(* Logix 5000 project; controller CIP_Sync_Essentials_Sample_Project_2_1 vendor 1 type 14 code 156 rev 34.11; software revision 34.01; part 4 of 4 *)
(* tags used below, declared in another part *)
   ax1_Cip_State_Machine : CIP_Axis_State_Machine;
   Ax1_Current_State : STRING;
   Ax1_Cyclic_Pos_Dis_AOI : CIP_Axis_Disable_Streaming;
   Ax1_Cyclic_Pos_Dis_Err_Description : STRING;
   Ax1_Cyclic_Pos_En_AOI : CIP_Axis_Enable_Streaming;
   Ax1_Cyclic_Pos_En_Err_Description : STRING;
   ax1_cyclic_position_off_request : BOOL;
   ax1_cyclic_position_on_request : BOOL;
   Ax1_Disable_AOI : CIP_Axis_Disable;
   Ax1_Disable_Error_Description : STRING;
   Ax1_Disable_Request_OS : BOOL;
   ax1_disable_streaming_os : BOOL;
   Ax1_Disable_Toggle : BOOL;
   Ax1_Enable_AOI : CIP_Axis_Enable;
   Ax1_Enable_Error_Description : STRING;
   Ax1_Enable_Request_OS : BOOL;
   ax1_enable_streaming_os : BOOL;
   Ax1_Enable_Toggle : BOOL;
   Ax1_Error_Message : STRING;
   Ax1_Extend : BOOL;
   ax1_extend_abs_move : MOTION_INSTRUCTION;
   Ax1_Extend_Target_Pos : DINT;
   Ax1_Fault_Reset_AOI : CIP_Axis_Fault_Reset;
   Ax1_Fault_Reset_Error_Description : STRING;
   Ax1_FAULT_RESET_OS : BOOL;
   Ax1_Fault_Reset_Toggle : BOOL;
   Ax1_Home : BOOL;
   Ax1_Home_AOI : CIP_Axis_Home;
   Ax1_Home_Error_Description : STRING;
   Ax1_Homed : BOOL;
   Ax1_Jog_Fwd : BOOL;
   Ax1_Jog_Rev : BOOL;
   AX1_MAJ1 : MOTION_INSTRUCTION;
   AX1_MAJ2 : MOTION_INSTRUCTION;
   Ax1_MAS1 : MOTION_INSTRUCTION;
   Ax1_Position_Cmd_Rsp_Assy : DINT;
   Ax1_Position_Fbk_Rsp_Assy : DINT;
   Ax1_Quick_Stop_Active : BOOL;
   Ax1_Quick_Stop_AOI : CIP_Axis_Quick_Stop;
   Ax1_Quick_Stop_Error_Description : STRING;
   Ax1_Quick_Stop_MSG : MESSAGE;
   Ax1_Quick_Stop_OS : BOOL;
   Ax1_Quick_Stop_Toggle : BOOL;
   Ax1_Retract : BOOL;
   ax1_retract_abs_move : MOTION_INSTRUCTION;
   ax1_start_home_ons : BOOL;
   Ax1_Stop_Cmd : BOOL;   // Axis Stop Command under normal streaming conditions
   Ax1_Stop_Cmd2 : BOOL;   // Axis Stop Command in the even the axis is disabled (disable or quick stop option code is 1 or 2) or disabled by fault
   Ax1_Stop_Cmd3 : BOOL;   // Axis Stop Command if streaming is disabled
   Ax1_Stop_OS : BOOL;
   Ax1_Stop_OS2 : BOOL;
   Ax1_Stop_OS3 : BOOL;
   Ax1_Streaming_Active : BOOL;
   Ax1_UnwindMsg : MESSAGE;
   Ax1_UpdatePeriodMsg : MESSAGE;
   Ax1_Virtual_Master_Actual_Position : DINT;
   Ax1_Virtual_Master_Cmd_Pos : DINT;
   Axis1_Disabled : BOOL;
   Axis1_Enabled : BOOL;
   Axis1_Faulted : BOOL;
   Axis1_Rotary : AXIS_VIRTUAL;
   AXIS_ONE : CIP_Axis;
   MotionGroup : MOTION_GROUP;

PROGRAM MainProgram   (* main routine MainRoutine_with_CIP_State_Machines *)

ROUTINE Axis1_Routine   (* ladder *)
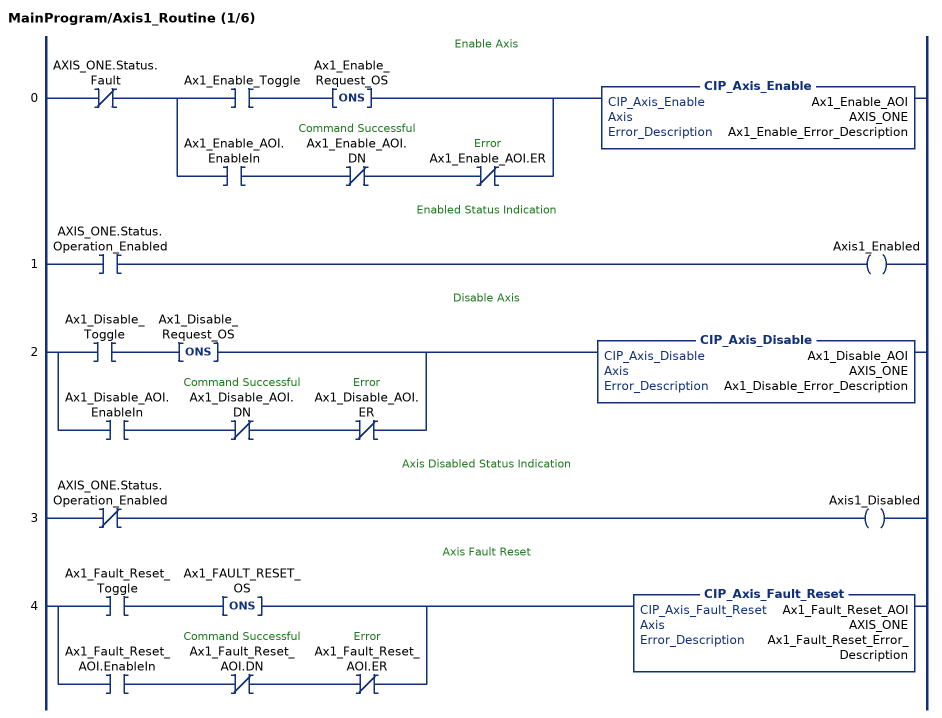
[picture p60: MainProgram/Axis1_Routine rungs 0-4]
   // Enable Axis
   0: XIO(AXIS_ONE.Status.Fault)[XIC(Ax1_Enable_Toggle) ONS(Ax1_Enable_Request_OS) ,XIC(Ax1_Enable_AOI.EnableIn) XIO(Ax1_Enable_AOI.DN) XIO(Ax1_Enable_AOI.ER) ]CIP_Axis_Enable(Ax1_Enable_AOI,AXIS_ONE,Ax1_Enable_Error_Description);
   // Enabled Status Indication
   1: XIC(AXIS_ONE.Status.Operation_Enabled)OTE(Axis1_Enabled);
   // Disable Axis
   2: [XIC(Ax1_Disable_Toggle) ONS(Ax1_Disable_Request_OS) ,XIC(Ax1_Disable_AOI.EnableIn) XIO(Ax1_Disable_AOI.DN) XIO(Ax1_Disable_AOI.ER) ]CIP_Axis_Disable(Ax1_Disable_AOI,AXIS_ONE,Ax1_Disable_Error_Description);
   // Axis Disabled Status Indication
   3: XIO(AXIS_ONE.Status.Operation_Enabled)OTE(Axis1_Disabled);
   // Axis Fault Reset
   4: [XIC(Ax1_Fault_Reset_Toggle) ONS(Ax1_FAULT_RESET_OS) ,XIC(Ax1_Fault_Reset_AOI.EnableIn) XIO(Ax1_Fault_Reset_AOI.DN) XIO(Ax1_Fault_Reset_AOI.ER) ]CIP_Axis_Fault_Reset(Ax1_Fault_Reset_AOI,AXIS_ONE,Ax1_Fault_Reset_Error_Description);
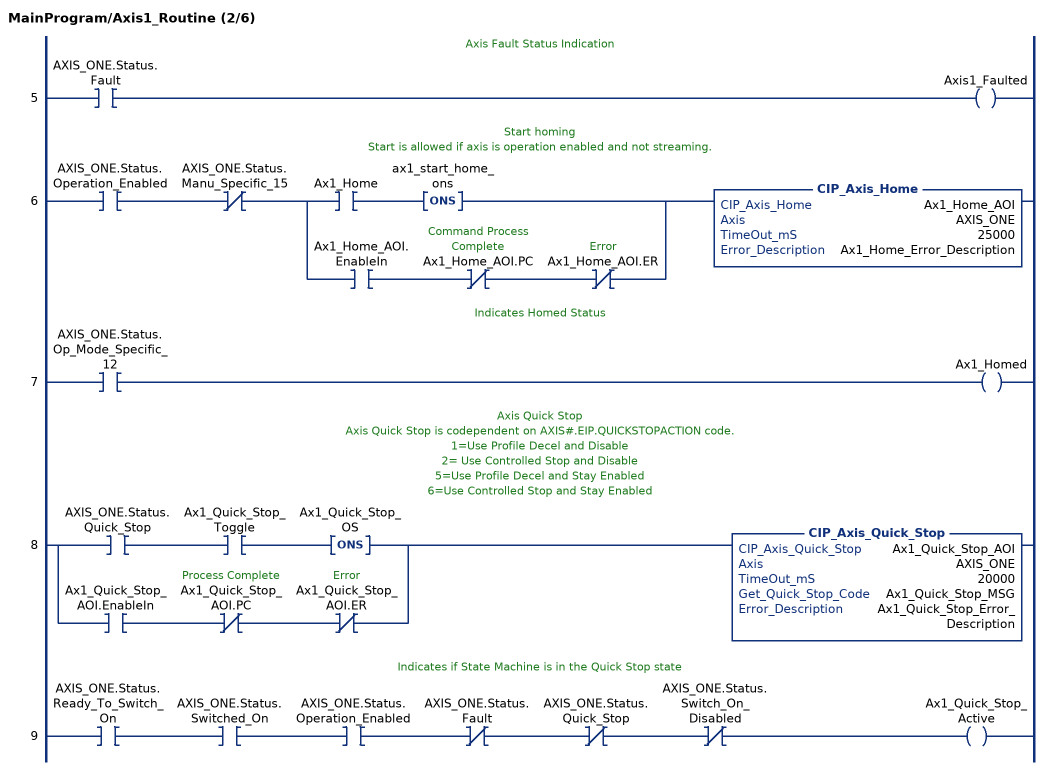
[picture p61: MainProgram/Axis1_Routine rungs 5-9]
   // Axis Fault Status Indication
   5: XIC(AXIS_ONE.Status.Fault)OTE(Axis1_Faulted);
   // Start homing
   // Start is allowed if axis is operation enabled and not streaming.
   6: XIC(AXIS_ONE.Status.Operation_Enabled)XIO(AXIS_ONE.Status.Manu_Specific_15)[XIC(Ax1_Home) ONS(ax1_start_home_ons) ,XIC(Ax1_Home_AOI.EnableIn) XIO(Ax1_Home_AOI.PC) XIO(Ax1_Home_AOI.ER) ]CIP_Axis_Home(Ax1_Home_AOI,AXIS_ONE,25000,Ax1_Home_Error_Description);
   // Indicates Homed Status
   7: XIC(AXIS_ONE.Status.Op_Mode_Specific_12)OTE(Ax1_Homed);
   // Axis Quick Stop
   // Axis Quick Stop is codependent on AXIS#.EIP.QUICKSTOPACTION code.
   // 1=Use Profile Decel and Disable
   // 2= Use Controlled Stop and Disable
   // 5=Use Profile Decel and Stay Enabled
   // 6=Use Controlled Stop and Stay Enabled
   8: [XIC(AXIS_ONE.Status.Quick_Stop) XIC(Ax1_Quick_Stop_Toggle) ONS(Ax1_Quick_Stop_OS) ,XIC(Ax1_Quick_Stop_AOI.EnableIn) XIO(Ax1_Quick_Stop_AOI.PC) XIO(Ax1_Quick_Stop_AOI.ER) ]CIP_Axis_Quick_Stop(Ax1_Quick_Stop_AOI,AXIS_ONE,20000,Ax1_Quick_Stop_MSG,Ax1_Quick_Stop_Error_Description);
   // Indicates if State Machine is in the Quick Stop state
   9: XIC(AXIS_ONE.Status.Ready_To_Switch_On)XIC(AXIS_ONE.Status.Switched_On)XIC(AXIS_ONE.Status.Operation_Enabled)XIO(AXIS_ONE.Status.Fault)XIO(AXIS_ONE.Status.Quick_Stop)XIO(AXIS_ONE.Status.Switch_On_Disabled)OTE(Ax1_Quick_Stop_Active);
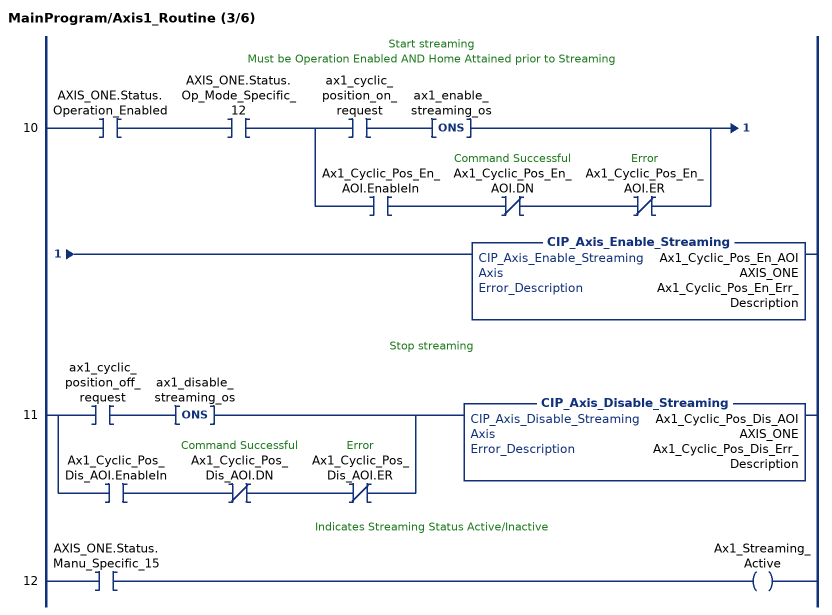
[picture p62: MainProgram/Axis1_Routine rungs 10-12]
   // Start streaming
   // Must be Operation Enabled AND Home Attained prior to Streaming
   10: XIC(AXIS_ONE.Status.Operation_Enabled)XIC(AXIS_ONE.Status.Op_Mode_Specific_12)[XIC(ax1_cyclic_position_on_request) ONS(ax1_enable_streaming_os) ,XIC(Ax1_Cyclic_Pos_En_AOI.EnableIn) XIO(Ax1_Cyclic_Pos_En_AOI.DN) XIO(Ax1_Cyclic_Pos_En_AOI.ER) ]CIP_Axis_Enable_Streaming(Ax1_Cyclic_Pos_En_AOI,AXIS_ONE,Ax1_Cyclic_Pos_En_Err_Description);
   // Stop streaming
   11: [XIC(ax1_cyclic_position_off_request) ONS(ax1_disable_streaming_os) ,XIC(Ax1_Cyclic_Pos_Dis_AOI.EnableIn) XIO(Ax1_Cyclic_Pos_Dis_AOI.DN) XIO(Ax1_Cyclic_Pos_Dis_AOI.ER) ]CIP_Axis_Disable_Streaming(Ax1_Cyclic_Pos_Dis_AOI,AXIS_ONE,Ax1_Cyclic_Pos_Dis_Err_Description);
   // Indicates Streaming Status Active/Inactive
   12: XIC(AXIS_ONE.Status.Manu_Specific_15)OTE(Ax1_Streaming_Active);
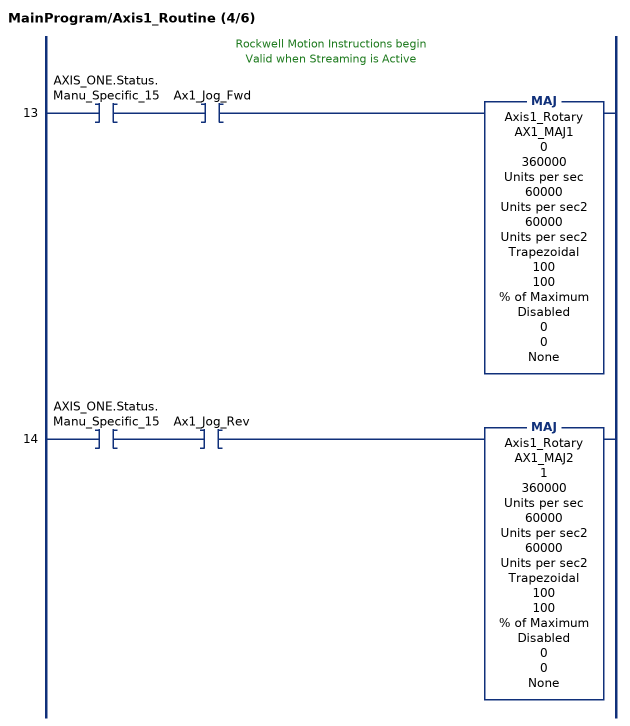
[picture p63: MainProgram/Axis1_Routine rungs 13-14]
   // Rockwell Motion Instructions begin
   // Valid when Streaming is Active
   13: XIC(AXIS_ONE.Status.Manu_Specific_15)XIC(Ax1_Jog_Fwd)MAJ(Axis1_Rotary,AX1_MAJ1,0,360000,Units per sec,60000,Units per sec2,60000,Units per sec2,Trapezoidal,100,100,% of Maximum,Disabled,0,0,None);
   14: XIC(AXIS_ONE.Status.Manu_Specific_15)XIC(Ax1_Jog_Rev)MAJ(Axis1_Rotary,AX1_MAJ2,1,360000,Units per sec,60000,Units per sec2,60000,Units per sec2,Trapezoidal,100,100,% of Maximum,Disabled,0,0,None);
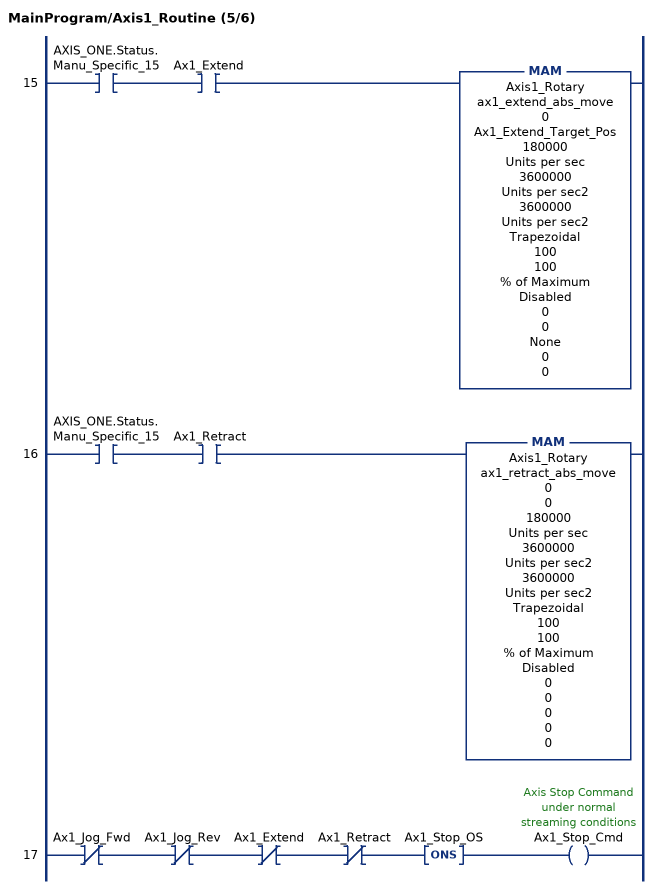
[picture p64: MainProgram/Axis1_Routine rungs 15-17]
   15: XIC(AXIS_ONE.Status.Manu_Specific_15)XIC(Ax1_Extend)MAM(Axis1_Rotary,ax1_extend_abs_move,0,Ax1_Extend_Target_Pos,180000,Units per sec,3600000,Units per sec2,3600000,Units per sec2,Trapezoidal,100,100,% of Maximum,Disabled,0,0,None,0,0);
   16: XIC(AXIS_ONE.Status.Manu_Specific_15)XIC(Ax1_Retract)MAM(Axis1_Rotary,ax1_retract_abs_move,0,0,180000,Units per sec,3600000,Units per sec2,3600000,Units per sec2,Trapezoidal,100,100,% of Maximum,Disabled,0,0,0,0,0);
   17: XIO(Ax1_Jog_Fwd)XIO(Ax1_Jog_Rev)XIO(Ax1_Extend)XIO(Ax1_Retract)ONS(Ax1_Stop_OS)OTE(Ax1_Stop_Cmd);
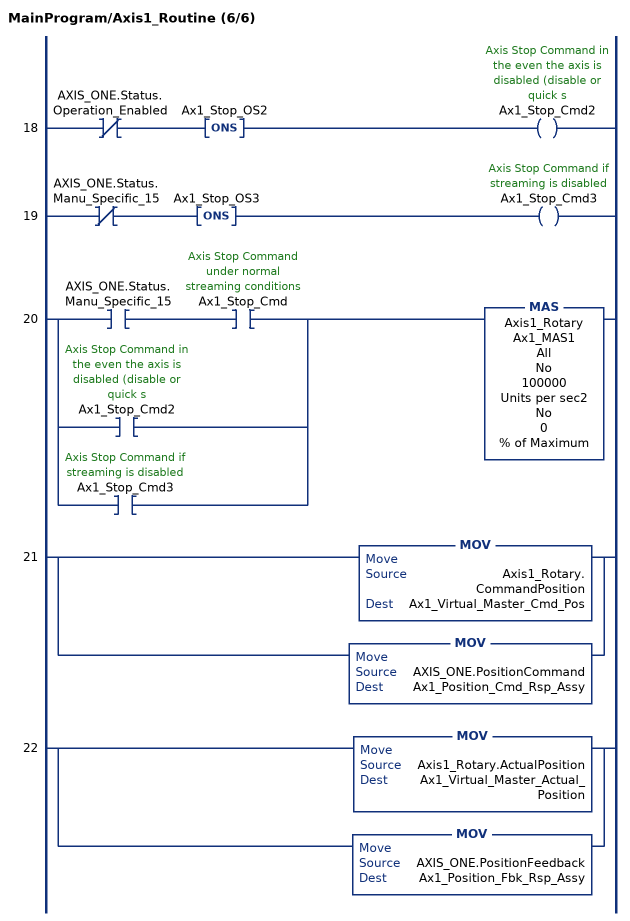
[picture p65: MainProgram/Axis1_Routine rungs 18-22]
   18: XIO(AXIS_ONE.Status.Operation_Enabled)ONS(Ax1_Stop_OS2)OTE(Ax1_Stop_Cmd2);
   19: XIO(AXIS_ONE.Status.Manu_Specific_15)ONS(Ax1_Stop_OS3)OTE(Ax1_Stop_Cmd3);
   20: [XIC(AXIS_ONE.Status.Manu_Specific_15) XIC(Ax1_Stop_Cmd) ,XIC(Ax1_Stop_Cmd2) ,XIC(Ax1_Stop_Cmd3) ]MAS(Axis1_Rotary,Ax1_MAS1,All,No,100000,Units per sec2,No,0,% of Maximum);
   21: [MOV(Axis1_Rotary.CommandPosition,Ax1_Virtual_Master_Cmd_Pos) ,MOV(AXIS_ONE.PositionCommand,Ax1_Position_Cmd_Rsp_Assy) ];
   22: [MOV(Axis1_Rotary.ActualPosition,Ax1_Virtual_Master_Actual_Position) ,MOV(AXIS_ONE.PositionFeedback,Ax1_Position_Fbk_Rsp_Assy) ];
END_ROUTINE

ROUTINE MainRoutine_with_CIP_State_Machines   (* ladder *)
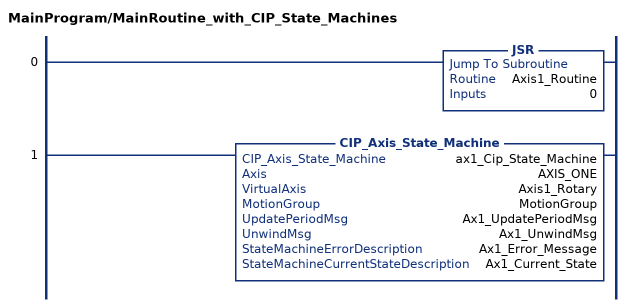
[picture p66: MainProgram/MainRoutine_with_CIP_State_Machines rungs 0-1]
   0: JSR(Axis1_Routine,0);
   1: CIP_Axis_State_Machine(ax1_Cip_State_Machine,AXIS_ONE,Axis1_Rotary,MotionGroup,Ax1_UpdatePeriodMsg,Ax1_UnwindMsg,Ax1_Error_Message,Ax1_Current_State);
END_ROUTINE
END_PROGRAM
